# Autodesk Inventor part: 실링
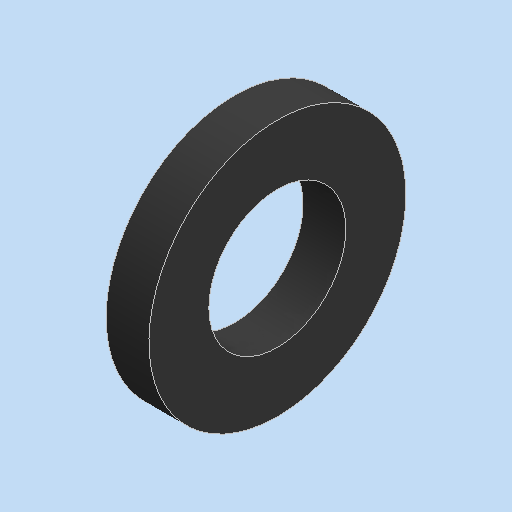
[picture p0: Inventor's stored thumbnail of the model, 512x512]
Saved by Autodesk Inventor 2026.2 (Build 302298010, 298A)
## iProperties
Created: 2026-03
Part Number: 실링
Material: 고무, 실리콘
Document SubType Name: Modeling
Designer: PC-2-06
Density: 1.25 g/cm^3
Appearance: 기본값
Author: jhkim
Sending System: Autodesk Inventor 2026
Preprocessor: ST-DEVELOPER v20.1
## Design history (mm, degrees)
feature "솔리드1"
node "솔리드2"
